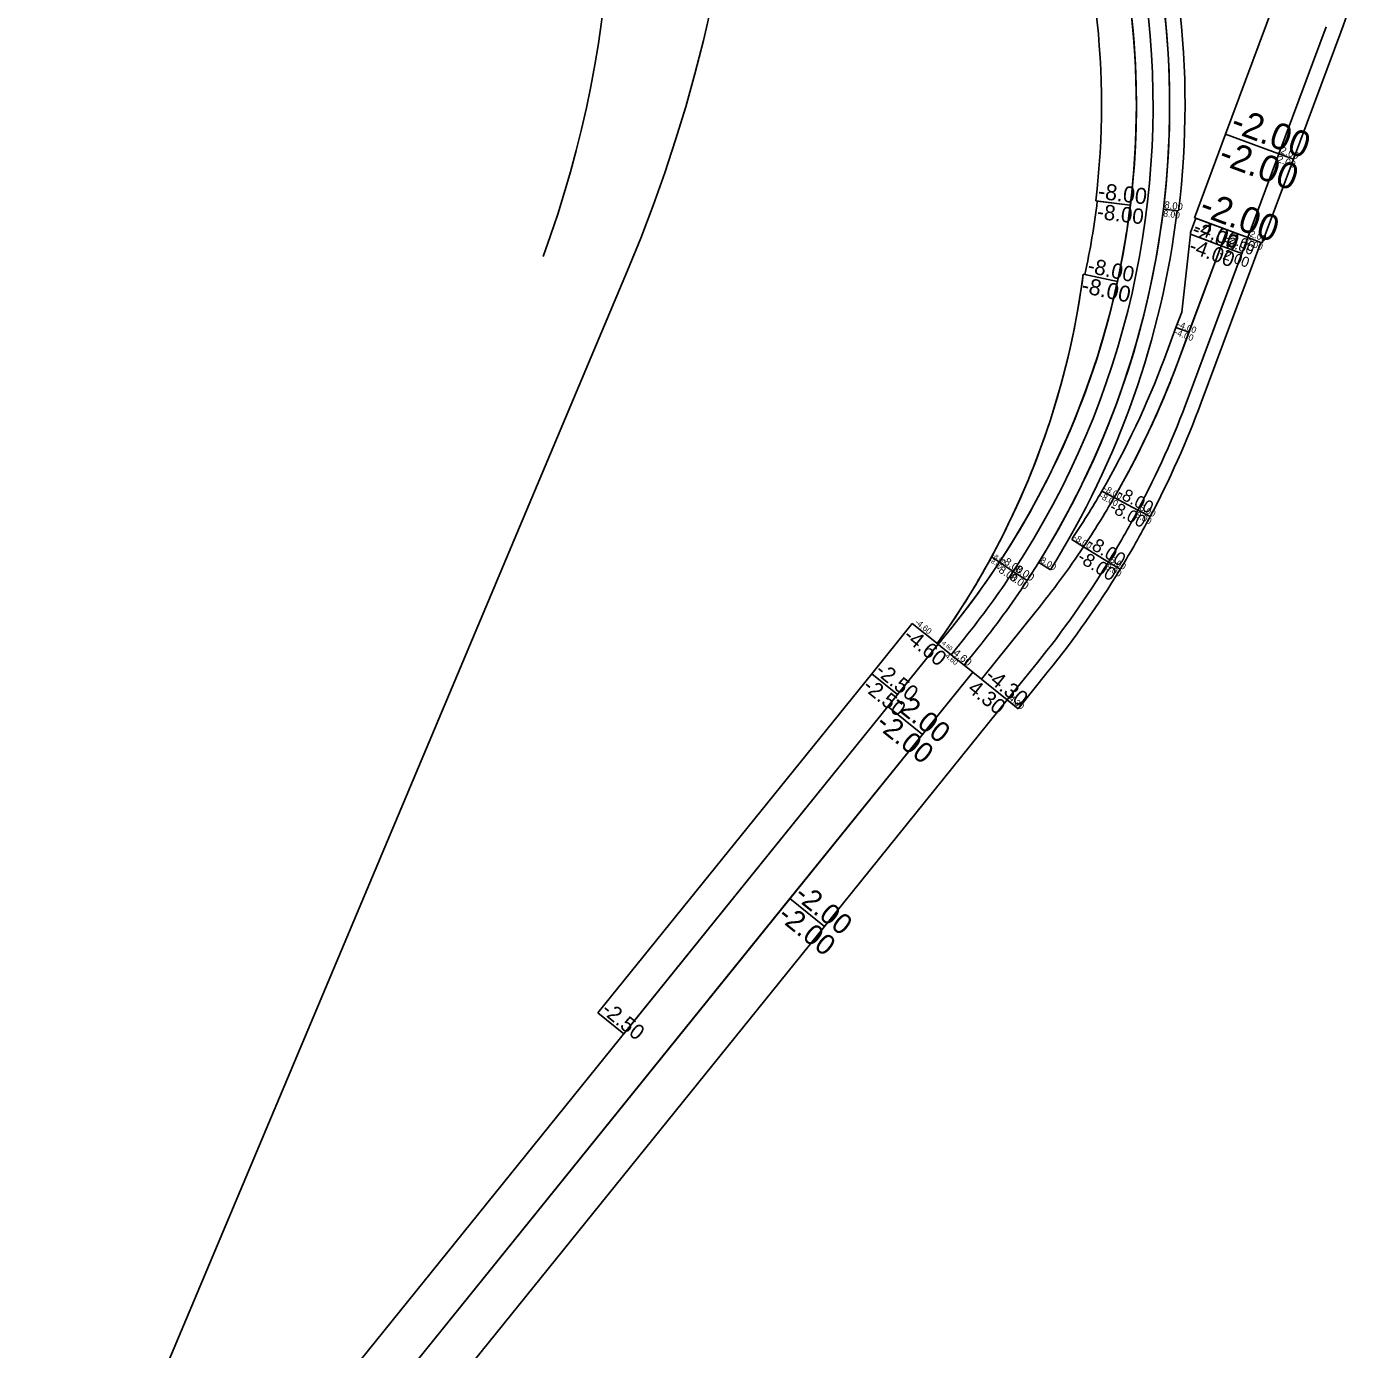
# Model space of a CAD drawing. Extents: x 2342222 to 2351711, y 366548 to 372860.
# Drawn here: x 2345982 to 2346953, y 368114 to 369068 of the extents above; entities that cross this region are included whole.
import ezdxf

# ---------------------------------------------------------------- set-up
doc = ezdxf.new("R2010")
doc.units = 0
for name, color, linetype in [('RD_HC_Cl', 7, 'Continuous'), ('RD_PD_Final_LnLine', 7, 'Continuous'), ('RD_PD_PaveShd', 7, 'Continuous'), ('RD_PD_SuperShp_LINE-A', 7, 'Continuous'), ('RD_PD_SuperShp_Line-B', 7, 'Continuous'), ('RD_PD_SuperShp_WP_CONN', 7, 'Continuous')]:
    doc.layers.add(name, color=color, linetype=linetype)

msp = doc.modelspace()

# ---------------------------------------------------------------- linework, layer by layer
at = {"layer": 'RD_HC_Cl'}
msp.add_line((2346414.93, 368892.18), (2346073.65, 368081.29), dxfattribs=at)
msp.add_line((2346414.93, 368892.18), (2346073.65, 368081.29), dxfattribs=at)
for centre, radius, start, end in [((2345401.07, 369318.89), 1100, 337.175, 58.13524), ((2345401.07, 369318.89), 1100, 337.175, 58.13524), ((2345603.44, 369178.93), 800, 339.77456, 51.32478), ((2345603.44, 369178.93), 800, 339.77456, 51.32478)]:
    msp.add_arc(centre, radius, start, end, dxfattribs=at)
at = {"layer": 'RD_PD_Final_LnLine'}
msp.add_arc((2346182.01, 369011.56), 600, 321.09378, 53.19179, dxfattribs=at)
at = {"layer": 'RD_PD_PaveShd'}
msp.add_arc((2346160.29, 368966.16), 588.44, 324.3401, 352.53038, dxfattribs=at)
at = {"layer": 'RD_PD_SuperShp_LINE-A'}
for p, q in [((2346880.42, 369082.26), (2346846.34, 368990.65)), ((2346884.88, 368976.31), (2346918.97, 369067.92)), ((2346918.97, 369067.92), (2346884.88, 368976.31)), ((2346895.31, 368972.43), (2346929.39, 369064.04)), ((2346846.34, 368990.65), (2346823.89, 368930.29)), ((2346846.34, 368990.65), (2346884.88, 368976.31)), ((2346884.88, 368976.31), (2346846.34, 368990.65)), ((2346862.43, 368915.95), (2346884.88, 368976.31)), ((2346884.88, 368976.31), (2346862.43, 368915.95)), ((2346884.88, 368976.31), (2346895.31, 368972.43)), ((2346895.31, 368972.43), (2346884.88, 368976.31)), ((2346872.86, 368912.07), (2346895.31, 368972.43)), ((2346824.94, 368929.9), (2346821.1, 368919.59)), ((2346823.89, 368930.29), (2346862.43, 368915.95)), ((2346847.43, 368921.53), (2346824.94, 368929.9)), ((2346820.97, 368918.34), (2346814.7, 368862.22)), ((2346821.1, 368919.59), (2346820.97, 368918.34)), ((2346820.97, 368918.34), (2346843.17, 368910.08)), ((2346843.17, 368910.08), (2346820.97, 368918.34)), ((2346847.43, 368921.53), (2346843.17, 368910.08)), ((2346843.17, 368910.08), (2346847.43, 368921.53)), ((2346862.43, 368915.95), (2346847.43, 368921.53)), ((2346843.17, 368910.08), (2346811.64, 368825.31)), ((2346862.43, 368915.95), (2346819.43, 368800.38)), ((2346819.94, 368847.62), (2346843.17, 368910.08)), ((2346828.8, 368796.89), (2346871.8, 368912.47)), ((2346858.17, 368904.5), (2346843.17, 368910.08)), ((2346843.17, 368910.08), (2346858.17, 368904.5)), ((2346858.17, 368904.5), (2346862.43, 368915.95)), ((2346862.43, 368915.95), (2346871.8, 368912.47)), ((2346871.8, 368912.47), (2346862.43, 368915.95)), ((2346871.8, 368912.47), (2346872.86, 368912.07)), ((2346819.43, 368800.38), (2346858.17, 368904.5)), ((2346814.7, 368862.22), (2346810.56, 368851.11)), ((2346810.56, 368851.11), (2346802.26, 368828.8)), ((2346810.56, 368851.11), (2346819.94, 368847.62)), ((2346819.94, 368847.62), (2346810.56, 368851.11)), ((2346811.64, 368825.31), (2346819.94, 368847.62)), ((2346757.15, 368733.03), (2346765.99, 368728.36)), ((2346765.99, 368728.36), (2346757.15, 368733.03)), ((2346765.99, 368728.36), (2346783.12, 368719.31)), ((2346783.12, 368719.31), (2346765.99, 368728.36)), ((2346783.12, 368719.31), (2346791.96, 368714.64)), ((2346791.96, 368714.64), (2346783.12, 368719.31)), ((2346735.36, 368698.05), (2346743.89, 368692.83)), ((2346743.89, 368692.83), (2346761.8, 368681.87)), ((2346761.8, 368681.87), (2346743.89, 368692.83)), ((2346761.8, 368681.87), (2346770.33, 368676.65)), ((2346770.33, 368676.65), (2346761.8, 368681.87)), ((2346709.83, 368646.52), (2346670.22, 368597.43)), ((2346688.89, 368582.35), (2346710.63, 368609.29)), ((2346710.63, 368609.29), (2346688.89, 368582.35)), ((2346670.22, 368597.43), (2346688.89, 368582.35)), ((2346696.67, 368576.07), (2346718.41, 368603.01)), ((2346688.89, 368582.35), (2346696.67, 368576.07))]:
    msp.add_line(p, q, dxfattribs=at)
for centre, radius, start, end in [((2346341.62, 369282.71), 627.13, 339.59346, 347.0341), ((2346211.8, 369048.47), 630, 329.95433, 339.59346), ((2346211.8, 369048.47), 640, 329.98862, 339.59346), ((2346211.8, 369048.47), 640, 337.81896, 339.59346), ((2346211.8, 369048.47), 640, 329.98862, 337.81896), ((2346178.36, 369038.87), 684, 332.14732, 339.59346), ((2346178.36, 369038.87), 684, 332.14732, 339.59346), ((2346178.36, 369038.87), 694, 332.14732, 339.59346), ((2346211.8, 369048.47), 630, 326.20547, 329.95433), ((2346211.8, 369048.47), 640, 326.24193, 329.98862), ((2346211.8, 369048.47), 640, 326.24193, 329.98862), ((2346178.36, 369038.87), 684, 328.53785, 332.14732), ((2346178.36, 369038.87), 684, 328.53785, 332.14732), ((2346178.36, 369038.87), 694, 328.53785, 332.14732), ((2346211.8, 369048.47), 640, 321.09378, 326.24193), ((2346178.36, 369038.87), 684, 321.09378, 328.53785), ((2346178.36, 369038.87), 684, 321.09378, 328.53785), ((2346178.36, 369038.87), 694, 321.09378, 328.53785)]:
    msp.add_arc(centre, radius, start, end, dxfattribs=at)
at = {"layer": 'RD_PD_SuperShp_Line-B'}
for p, q in [((2346752.71, 368942.39), (2346777.65, 368939.36)), ((2346777.65, 368939.36), (2346753.83, 368942.25)), ((2346811.41, 368935.27), (2346801.48, 368936.48)), ((2346801.48, 368936.48), (2346812.52, 368935.14)), ((2346768.37, 368884.32), (2346743.73, 368889.66)), ((2346768.37, 368884.32), (2346743.73, 368889.66)), ((2346744.91, 368889.41), (2346768.37, 368884.32)), ((2346677.48, 368685.51), (2346683.23, 368681.73)), ((2346683.23, 368681.73), (2346677.48, 368685.51)), ((2346693.25, 368675.13), (2346683.23, 368681.73)), ((2346693.25, 368675.13), (2346683.23, 368681.73)), ((2346703.27, 368668.54), (2346693.25, 368675.13)), ((2346703.27, 368668.54), (2346693.25, 368675.13)), ((2346711.61, 368681.54), (2346720.09, 368676.25)), ((2346648.92, 368634.73), (2346639.09, 368622.55)), ((2346639.09, 368622.55), (2346648.92, 368634.73)), ((2346648.43, 368615.01), (2346658.26, 368627.19)), ((2346658.26, 368627.19), (2346648.43, 368615.01)), ((2346638.39, 368623.11), (2346639.09, 368622.55)), ((2346639.09, 368622.55), (2346641.05, 368620.96)), ((2346641.05, 368620.96), (2346648.43, 368615.01)), ((2346657.76, 368607.47), (2346667.59, 368619.65)), ((2346648.43, 368615.01), (2346657.76, 368607.47))]:
    msp.add_line(p, q, dxfattribs=at)
for centre, radius, start, end in [((2346182.01, 369011.56), 635.13, 353.08954, 47.63463), ((2346182.01, 369011.56), 624, 326.65285, 47.63463), ((2346182.01, 369011.56), 624, 353.08954, 47.63463), ((2346182.01, 369011.56), 612, 326.65285, 47.63463), ((2346182.01, 369011.56), 612, 326.65285, 47.63463), ((2346182.01, 369011.56), 600, 326.65285, 47.63463), ((2346182.01, 369011.56), 600, 353.08954, 47.63463), ((2346182.01, 369011.56), 574.88, 353.08954, 47.63463), ((2346182.01, 369011.56), 624, 328.0712, 353.08942), ((2346182.01, 369011.56), 576, 347.7568, 353.08954), ((2346182.01, 369011.56), 600, 347.7568, 353.08942), ((2346182.01, 369011.56), 634, 328.07086, 353.08942), ((2346160.29, 368966.16), 588.44, 331.51421, 352.53038), ((2346182.01, 369011.56), 600, 326.65285, 347.7568), ((2346160.29, 368966.16), 588.44, 324.3401, 331.51421), ((2346182.01, 369011.56), 600, 321.09378, 326.65285), ((2346182.01, 369011.56), 600, 321.09378, 326.65285), ((2346182.01, 369011.56), 612, 321.09378, 326.65285), ((2346182.01, 369011.56), 612, 321.09378, 326.65285), ((2346182.01, 369011.56), 624, 321.09378, 326.65285)]:
    msp.add_arc(centre, radius, start, end, dxfattribs=at)
at = {"layer": 'RD_PD_SuperShp_WP_CONN'}
for p, q in [((2346620.41, 368637.62), (2346591.1, 368601.3)), ((2346639.09, 368622.54), (2346620.41, 368637.62)), ((2346639.09, 368622.55), (2346602.8, 368577.58)), ((2346609.77, 368586.23), (2346639.09, 368622.54)), ((2346641.05, 368620.96), (2346639.09, 368622.55)), ((2346657.76, 368607.47), (2346641.05, 368620.96)), ((2346663.99, 368602.45), (2346657.76, 368607.47)), ((2346591.1, 368601.3), (2346393.59, 368356.58)), ((2346663.99, 368602.45), (2346532.1, 368439.03)), ((2346591.1, 368601.3), (2346609.77, 368586.23)), ((2346609.77, 368586.23), (2346591.1, 368601.3)), ((2346627.7, 368557.48), (2346663.99, 368602.45)), ((2346670.21, 368597.42), (2346663.99, 368602.45)), ((2346688.89, 368582.35), (2346670.21, 368597.42)), ((2346602.8, 368577.58), (2346160.3, 368029.31)), ((2346412.27, 368341.51), (2346609.77, 368586.23)), ((2346557, 368418.93), (2346688.89, 368582.35)), ((2346602.8, 368577.58), (2346627.7, 368557.48)), ((2346627.7, 368557.48), (2346602.8, 368577.58)), ((2346185.2, 368009.21), (2346627.7, 368557.48)), ((2346532.1, 368439.03), (2346059.28, 367853.19)), ((2346557, 368418.93), (2346532.1, 368439.03)), ((2346532.1, 368439.03), (2346557, 368418.93)), ((2346084.18, 367833.09), (2346557, 368418.93)), ((2346393.59, 368356.58), (2346412.27, 368341.51))]:
    msp.add_line(p, q, dxfattribs=at)

# ---------------------------------------------------------------- texts
at = {"layer": 'RD_PD_SuperShp_LINE-A'}
for s, height, rotation, p in [('-2.00', 18.918, 339.59346, (2346848.89, 368992.78)), ('-2.00', 18.918, 339.59346, (2346840.28, 368969.65)), ('2.00', 5.117, 339.59346, (2346883.25, 368970.63)), ('2.00', 5.117, 339.59346, (2346885.57, 368976.89)), ('-2.00', 18.917, 339.59346, (2346826.43, 368932.42)), ('-2.00', 11.04, 339.59346, (2346821.4, 368917.64)), ('-4.00', 10.9, 339.59346, (2346822.43, 368919.57)), ('-2.00', 7.36, 339.59346, (2346845.08, 368913.36)), ('2.00', 4.6, 339.59346, (2346863.53, 368916.91)), ('-4.00', 10.9, 339.59346, (2346819.16, 368905.84)), ('-2.00', 7.36, 339.59346, (2346840.82, 368901.91)), ('-2.00', 7.36, 339.59346, (2346844.16, 368910.91)), ('2.00', 4.6, 339.59426, (2346860.96, 368910.85)), ('-4.00', 4.6, 339.59346, (2346809.09, 368846)), ('-4.00', 4.6, 339.59346, (2346811.18, 368851.63)), ('-8.00', 4.603, 332.14732, (2346757.93, 368733.41)), ('-8.00', 8.909, 332.14732, (2346767.31, 368729.19)), ('-8.00', 4.603, 332.14732, (2346754.92, 368728.21)), ('-8.00', 8.909, 332.14732, (2346761.88, 368718.92)), ('8.00', 4.6, 332.14732, (2346783.8, 368719.74)), ('8.00', 4.6, 332.14732, (2346780.99, 368714.44)), ('-8.00', 4.604, 328.53785, (2346736.16, 368698.37)), ('-8.00', 9.657, 328.53785, (2346745.37, 368693.64)), ('-8.00', 9.657, 328.53785, (2346738.59, 368683.03)), ('8.00', 4.6, 328.53785, (2346762.51, 368682.26)), ('8.00', 4.6, 328.53785, (2346759.37, 368677.14)), ('-4.30', 11.04, 321.0924, (2346672.02, 368598.13)), ('4.30', 4.6, 321.09047, (2346689.64, 368582.65))]:
    msp.add_text(s, height=height, rotation=rotation, dxfattribs=at).set_placement(p)
at = {"layer": 'RD_PD_SuperShp_Line-B'}
for s, height, rotation, p in [('-8.00', 11.558, 353.08954, (2346753.92, 368944.01)), ('-8.00', 11.04, 353.0866, (2346753.25, 368929.51)), ('8.00', 5.117, 353.08954, (2346802.01, 368937.2)), ('8.00', 4.6, 353.08942, (2346801.24, 368931.17)), ('-8.00', 11.04, 347.7568, (2346746.2, 368890.85)), ('-8.00', 11.597, 347.7666, (2346741.88, 368876.39)), ('-8.00', 3.162, 326.65285, (2346675.71, 368682.31)), ('-8.00', 3.162, 326.65285, (2346677.98, 368685.76)), ('-8.00', 5.52, 326.65285, (2346684.09, 368682.17)), ('8.00', 4.6, 328.04957, (2346712.31, 368681.93)), ('-8.00', 5.52, 326.65285, (2346680.13, 368676.15)), ('8.00', 5.52, 326.65285, (2346694.11, 368675.57)), ('8.00', 5.52, 326.65285, (2346690.15, 368669.56)), ('-4.60', 4.348, 321.09378, (2346621.97, 368637.76)), ('-4.60', 0.415, 321.11724, (2346638.45, 368623.14)), ('-4.60', 3, 321.08539, (2346640.53, 368623.64)), ('4.60', 5.52, 321.09378, (2346649.33, 368615.36))]:
    msp.add_text(s, height=height, rotation=rotation, dxfattribs=at).set_placement(p)
at = {"layer": 'RD_PD_SuperShp_WP_CONN'}
for s, height, rotation, p in [('-4.60', 11.04, 321.08259, (2346613.17, 368627.12)), ('-4.60', 3.68, 321.06287, (2346642.51, 368614.54)), ('-2.50', 11.04, 321.09378, (2346592.9, 368602)), ('-2.50', 11.04, 321.09378, (2346583.86, 368590.8)), ('4.30', 11.04, 321.09378, (2346659.63, 368589.13)), ('-2.00', 14.72, 321.09378, (2346605.2, 368578.52)), ('-2.00', 14.72, 321.09378, (2346593.14, 368563.58)), ('-2.00', 14.72, 321.09378, (2346534.5, 368439.97)), ('-2.00', 14.72, 321.09378, (2346522.44, 368425.03)), ('-2.50', 11.04, 321.09378, (2346395.39, 368357.28))]:
    msp.add_text(s, height=height, rotation=rotation, dxfattribs=at).set_placement(p)

doc.saveas('drawing.dxf')
